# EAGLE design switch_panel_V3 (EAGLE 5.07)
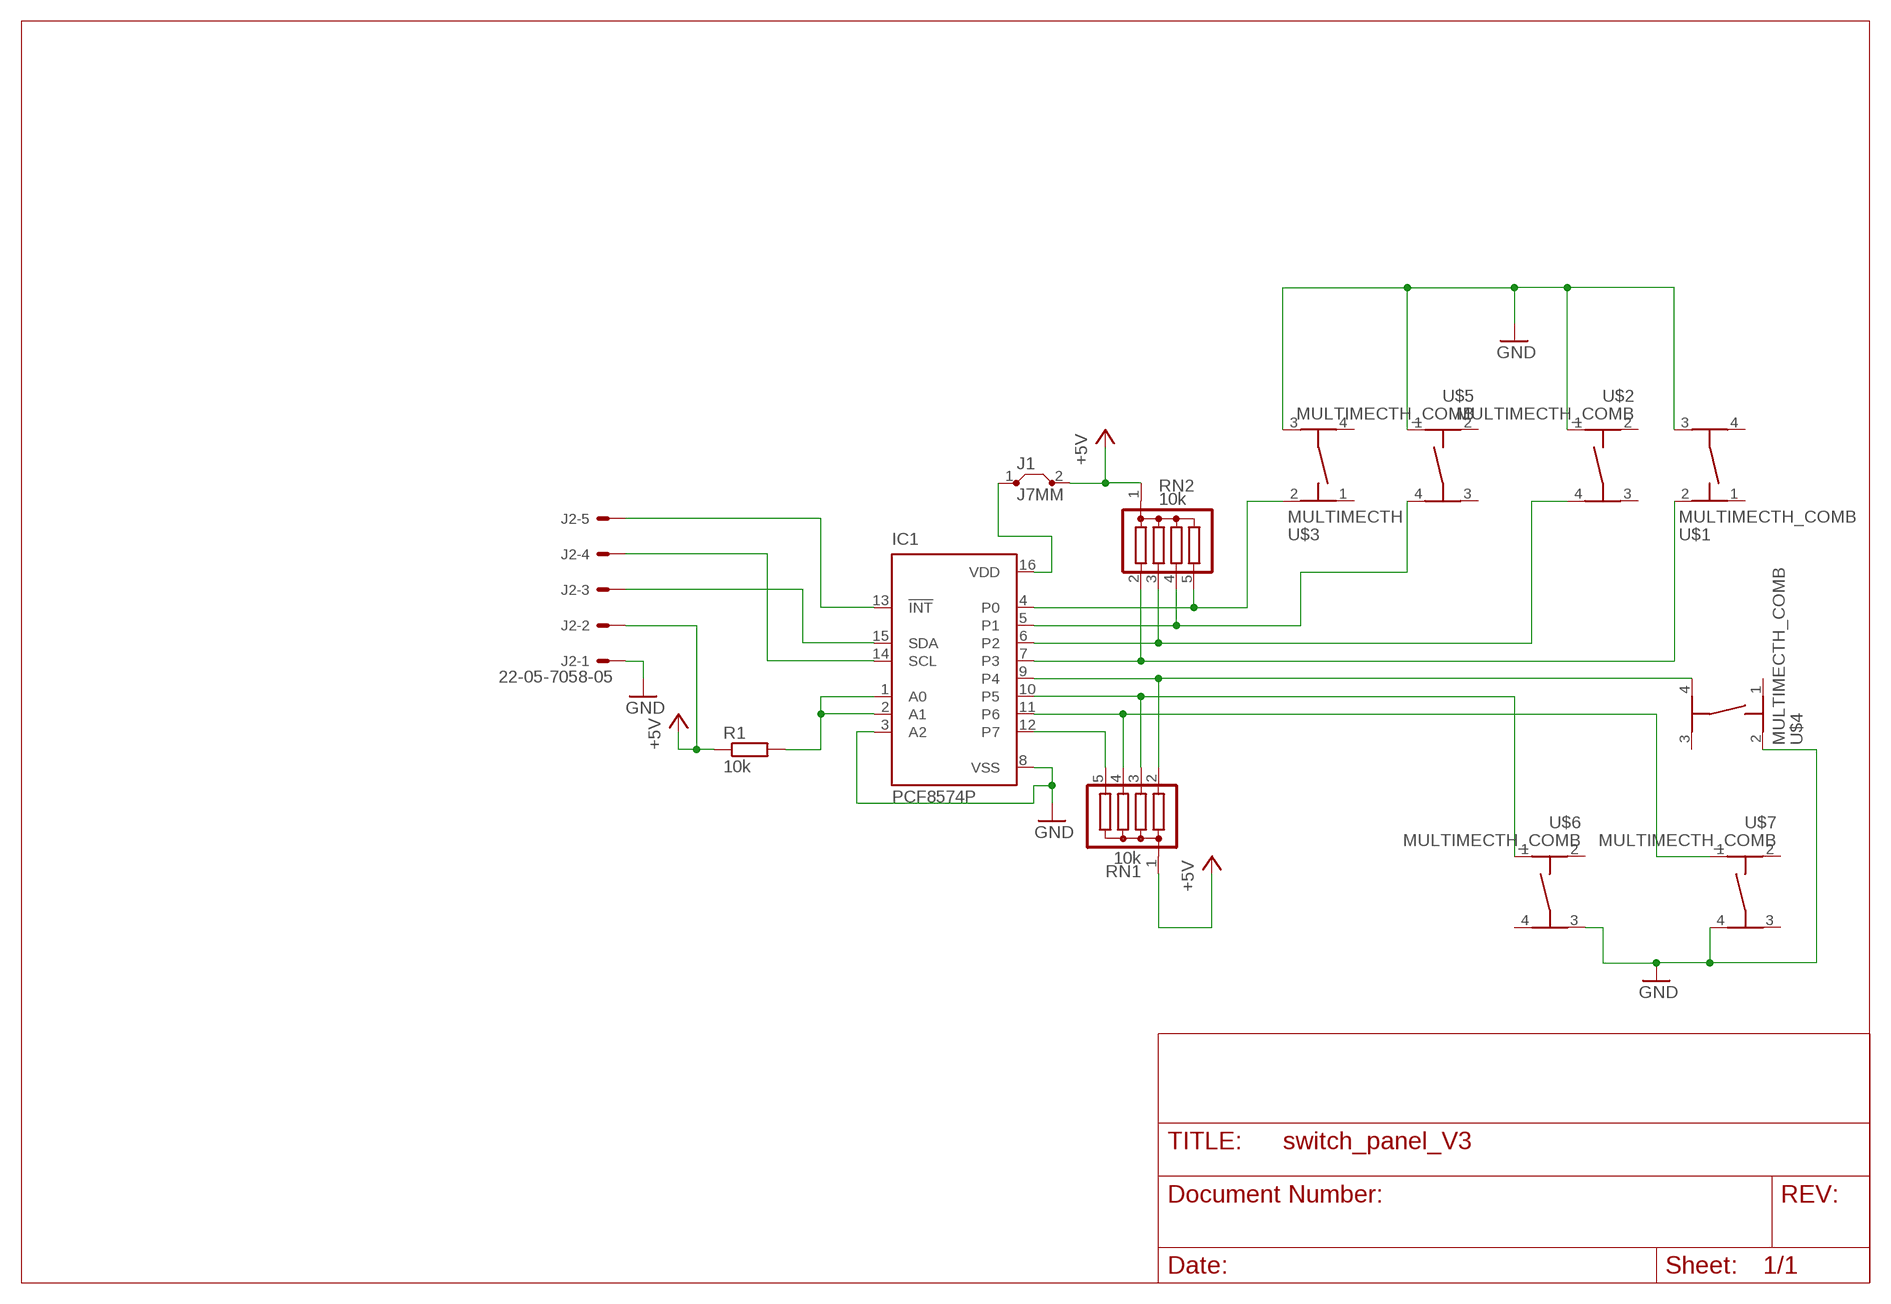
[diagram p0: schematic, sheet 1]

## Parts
IC1  PCF8574P  [DIL16]
J1  J7MM  [07]
J2  22-05-7058-05  [7395-05]
R1  10k  R-EU_0207/7  [0207/7]
RN1  10k  G04R  [SIL5]
RN2  10k  G04R  [SIL5]
U$1  MULTIMECTH_COMB  [MULTIMEC_COMB]
U$2  MULTIMECTH_COMB  [MULTIMEC_COMB]
U$3  MULTIMECTH  [MULTIMEC_TH]
U$4  MULTIMECTH_COMB  [MULTIMEC_COMB]
U$5  MULTIMECTH_COMB  [MULTIMEC_COMB]
U$6  MULTIMECTH_COMB  [MULTIMEC_COMB]
U$7  MULTIMECTH_COMB  [MULTIMEC_COMB]

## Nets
+5V: J1.2 J2.2 R1.1 RN1.1 RN2.1
GND: IC1.3(A2) IC1.8(VSS) J2.1 U$1.3 U$2.1 U$3.3 U$4.2 U$5.1 U$6.3 U$7.4
N$1: IC1.15(SDA) J2.3
N$2: IC1.16(VDD) J1.1
N$3: IC1.14(SCL) J2.4
N$4: IC1.13(!INT) J2.5
N$5: IC1.1(A0) IC1.2(A1) R1.2
N$6: IC1.9(P4) RN1.2 U$4.4
N$7: IC1.10(P5) RN1.3 U$6.1
N$8: IC1.11(P6) RN1.4 U$7.1
N$9: IC1.12(P7) RN1.5
N$11: IC1.7(P3) RN2.2 U$1.2
N$12: IC1.6(P2) RN2.3 U$2.4
N$13: IC1.5(P1) RN2.4 U$5.4
N$14: IC1.4(P0) RN2.5 U$3.2
Unconnected: U$1.1 U$1.4 U$2.2 U$2.3 U$3.1 U$3.4 U$4.1 U$4.3 U$5.2 U$5.3 U$6.2 U$6.4 U$7.2 U$7.3

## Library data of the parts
IC1 = micro-philips:PCF8574: I2C-Bus Remote 8-bit I/O expander http://www.semiconductors.philips.com/acrobat_download/datasheets/PCF8574_4.pdf
J1 = jumper:J: Bridge
J2 = con-molex:22-?-05: CONNECTOR wire to board 2.54 mm (.1 inch) pitch header
R1 = rcl:R-EU_: RESISTOR, European symbol
RN1 RN2 = resistor-sil:G04R: SIL RESISTOR
U$1-U$7 = taster:MULTIMEC: multimec switch smd type

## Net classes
0 default: width 1.016 mm, clearance 0.737 mm

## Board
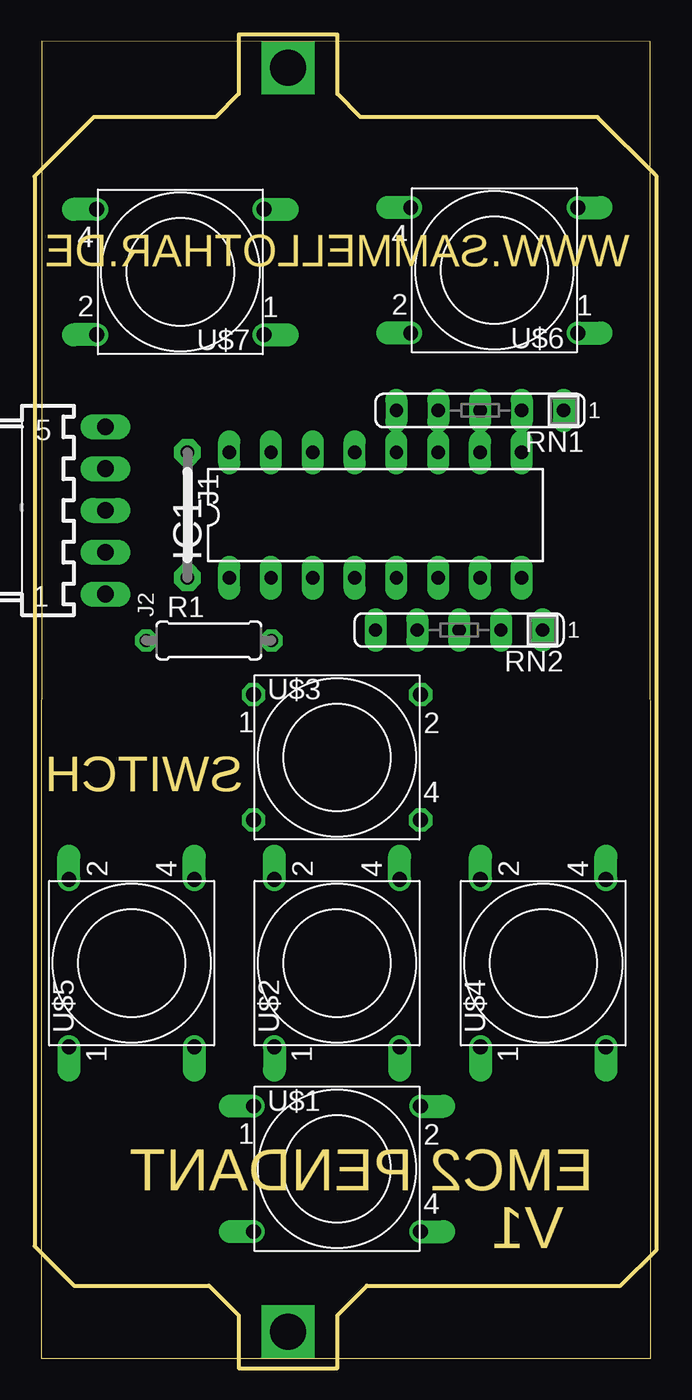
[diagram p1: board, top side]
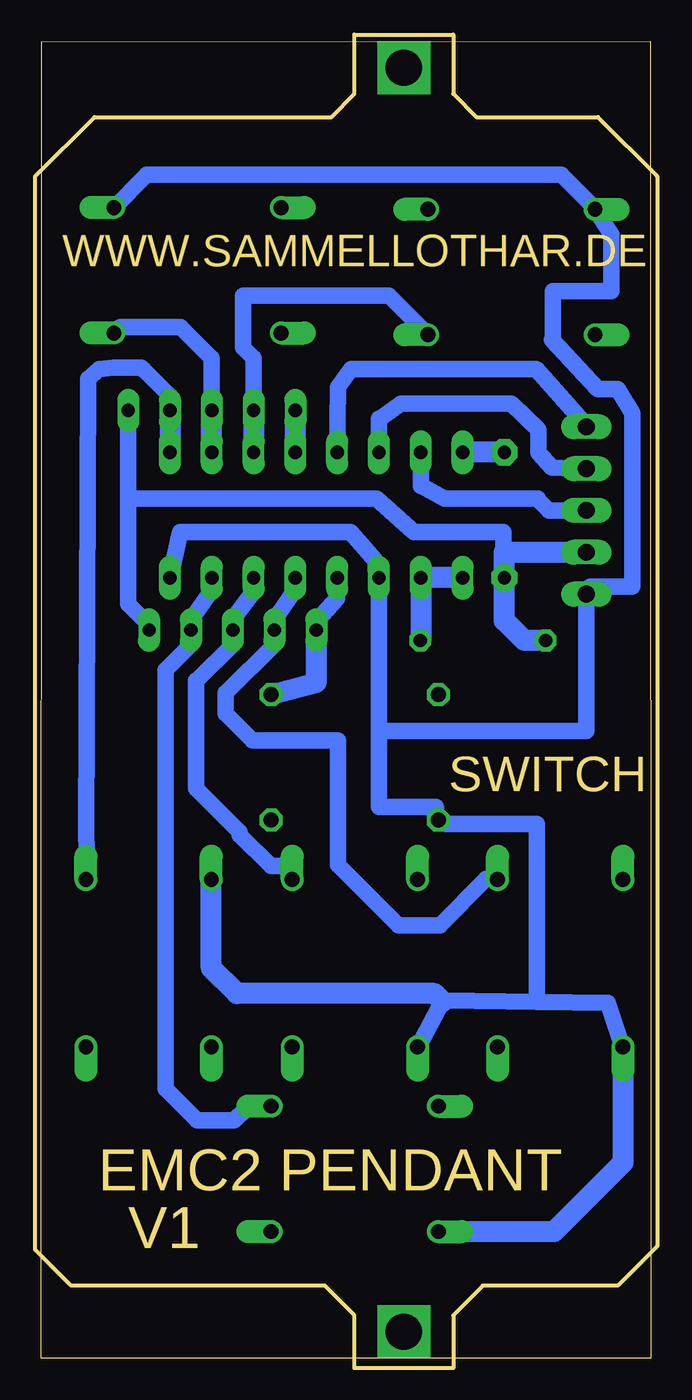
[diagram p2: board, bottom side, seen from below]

Size 37.04 x 80 mm. Coordinates in mm from the lower left corner, seen from the top.
Outline: 0,0 37.04,0 37.01,79.97 0.03,80 0,0
Copper layers (1*16): Top 0.035mm / dielectric 1.5mm / Bottom 0.035mm
Design rules "default *": minimum track width 25mil, minimum drill 24mil, track to track 8mil, track to pad 8mil, pad to pad 8mil, via to via 8mil, smd to smd 8mil, copper to edge 20mil, drill to drill 8mil, minimum pad ring 10mil, minimum via ring 8mil, stop-mask expansion 4mil, vias tented up to drill 0mil, thermal gap 10mil
Milling: 20 lines

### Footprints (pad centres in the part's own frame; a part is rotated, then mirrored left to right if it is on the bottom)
DIL16 = drill 0.813 long: 1 -8.89,-3.81; 2 -6.35,-3.81; 3 -3.81,-3.81; 4 -1.27,-3.81; 5 1.27,-3.81; 6 3.81,-3.81; 7 6.35,-3.81; 8 8.89,-3.81; 9 8.89,3.81; 10 6.35,3.81; 11 3.81,3.81; 12 1.27,3.81; 13 -1.27,3.81; 14 -3.81,3.81; 15 -6.35,3.81; 16 -8.89,3.81
07 = drill 0.813 pad 1.6 octagon: 1 -3.81,0; 2 3.81,0
7395-05 = drill 1.016 long: 1 5.08,0; 2 2.54,0; 3 0,0; 4 -2.54,0; 5 -5.08,0
0207/7 = drill 0.813 octagon: 1 -3.81,0; 2 3.81,0
SIL5 = drill 0.813 long: 1 -5.08,0; 2 -2.54,0; 3 0,0; 4 2.54,0; 5 5.08,0
MULTIMEC_COMB = drill 0.9 offset: 1 -5.08,3.81; 2 5.08,3.81; 3 -5.08,-3.81; 4 5.08,-3.81
MULTIMEC_TH = drill 0.9 octagon: 1 -5.08,3.81; 2 5.08,3.81; 3 -5.08,-3.81; 4 5.08,-3.81

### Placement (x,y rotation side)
IC1  20.32,51.22 0 top
J1  8.89,51.22 270 top
J2  3.91,51.5 270 top
R1  10.19,43.6 0 top
RN1  26.67,57.57 180 top
RN2  25.4,44.23 180 top
U$1  17.98,11.5 0 top
U$2  17.98,24 90 top
U$3  17.98,36.5 0 top
U$4  30.51,24 90 top
U$5  5.5,24 90 top
U$6  27.54,66.09 180 top
U$7  8.46,65.99 180 top

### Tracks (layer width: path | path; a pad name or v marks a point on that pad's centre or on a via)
+5V
  Bottom 1.016: J1.2 8.94,47.41 8.94,50.19 14.38,50.19 16.66,52.22 31.55,52.22 | 31.55,52.22 31.75,52.22 RN1.1 | RN2.1 30.48,44.55 31.75,45.82 31.75,52.02 31.55,52.22
  Bottom 1.27: R1.1 7.68,43.6 8.89,44.81 J1.2 8.89,48.96 | 8.89,48.96 J2.2 | 8.89,48.96 8.89,48.97
GND
  Bottom 0.965: 12.9,33 12.9,32.72 12.88,32.7 U$3.3 | U$1.3
  Bottom 1.016: 6.91,21.64 12.6,21.74 12.64,21.66 14.12,18.95 U$2.1 | 6.91,21.64 2.59,21.59 1.73,18.95 U$5.1 | U$6.3 30.63,71.88 5.44,71.88 3.4,69.85 U$7.4 2.39,68.28 2.39,64.82 5.94,64.82 5.94,61.87 5.99,61.87 3.2,58.88 1.98,58.88 1.12,57.4 1.12,46.89 3.66,46.89 J2.1 3.91,46.38 3.91,38.1 16.51,38.1 | 16.51,38.1 16.51,33.48 13.06,33.48 13.06,32.85 U$3.3 12.68,32.69 12.45,32.46 6.91,32.46 6.91,21.64 | 16.51,38.1 IC1.3 16.71,47.9 16.71,48.46 18.24,50.19 28.6,50.19 IC1.8
  Bottom 1.27: U$1.3 5.87,7.69 1.68,11.89 1.68,18.91 U$5.1 | U$4.2 26.7,23.7 25.15,22.15 13.13,22.15 12.64,21.66
N$1
  Bottom 1.016: J2.3 6.2,51.5 6.86,52.16 6.86,52.22 12.54,52.22 13.9,52.98 13.96,52.98 IC1.15
N$2
  Bottom 1.27: J1.1 IC1.16
N$3
  Bottom 1.016: J2.4 4.74,54.04 6,54.1 6.82,55 6.82,56.4 8.46,57.98 15.18,57.98 16.44,57.08 16.5,57.08 IC1.14
N$4
  Bottom 1.016: J2.5 3.84,56.58 6.96,60.1 18.2,60.1 19,59 19.04,56.86 IC1.13
N$5
  Bottom 1.27: R1.2 13.97,43.6 IC1.2 IC1.1
N$6
  Bottom 0.991: U$4.4 34.32,30.68 34.3,30.78 34.46,30.44 34.21,29.13 34.3,31.81 34.2,59.5 33.5,60.1 32.62,60.18 30.96,60.18 30.84,60.06 30.82,60.06 29.16,58.4 29.16,58.2 RN1.2
  Bottom 1.27: RN1.2 IC1.9
N$7
  Bottom 1.016: RN1.3 26.67,60.74 28.57,62.65 32.25,62.65 U$6.1
  Bottom 1.27: IC1.10 RN1.3
N$8
  Bottom 1.016: RN1.4 24.13,60.74 24.77,61.38 24.77,64.56 15.91,64.56 U$7.1
  Bottom 1.27: RN1.4 IC1.11
N$9
  Bottom 1.27: IC1.12 RN1.5
N$10  (via drill 2.2)
  other vias: 15,78.4
N$11
  Bottom 0.991: U$1.2 23.24,15.12 24.62,15.12 25.3,14.44 27.56,14.44 29.48,16.36 29.48,41.82 27.9,43.4 27.9,43.74 RN2.2
  Bottom 1.016: RN2.2 27.94,44.87 26.67,46.64 IC1.7
N$12
  Bottom 0.991: U$2.4 21.8,29.9 23.08,29.9 24.98,31.8 24.98,31.98 27.62,34.62 27.62,41.16 27.6,41.16 25.36,43.4 25.36,43.74 RN2.3
  Bottom 1.016: RN2.3 25.4,44.87 24.23,46.44 IC1.6
N$13
  Bottom 0.991: U$5.4 9.34,29.1 10.02,29.1 12.82,26.3 15.32,26.3 19,29.98 19,37.52 24.2,37.52 25.84,39.16 25.84,40.4 25.82,40.4 22.82,43.4 22.82,43.74 RN2.4
  Bottom 1.016: RN2.4 22.86,44.87 21.69,46.54 IC1.5
N$14
  Bottom 1.016: RN2.5 20.22,44.87 19.05,46.14 IC1.4
  Bottom 1.27: U$3.2 20.32,41.06 RN2.5
N$15  (via drill 2.2)
  other vias: 15,1.6

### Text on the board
Milling: WWW.SAMMELLOTHAR.DE | SWITCH | EMC2 PENDANT | V1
